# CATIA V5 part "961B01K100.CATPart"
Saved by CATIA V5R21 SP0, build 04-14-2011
Part number: 961B01K100
Bounding box of the stored display mesh (mm): x -18.1 to 18.1, y -25 to 75, z -10 to 4.5
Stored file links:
  C:\Users\ALI OZGUN\Desktop\alhan\961B01K100.CATPart
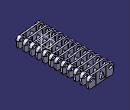
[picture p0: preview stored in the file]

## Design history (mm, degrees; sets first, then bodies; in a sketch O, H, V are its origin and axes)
Body1 (main body)
  Sketch1 on zx-plane, origin (0, 0, 0), H (-1, 0, 0), V (0, 0, 1)
    construction line L1 (-13.6, 0) -> (13.6, 0)
    point P1 (-13.6, 0)
    line L2 (-13.6, 4.5) -> (13.6, 4.5)
    line L3 (13.6, -4.5) -> (-13.6, -4.5)
    arc A1 centre (13.6, 0) radius 4.5 from (13.6, 4.5) to (13.6, -4.5) cw
    arc A2 centre (-13.6, 0) radius 4.5 from (-13.6, -4.5) to (-13.6, 4.5) cw
    distance L1 L2 = 4.5
    length L1 = 27.2
    distance P1 V = 13.6
    coincidence: P1 H
    horizontal: L1 H
    tangency: A1 L2, A2 L2, A1 L3, A2 L3
  Sketch2 on zx-plane, origin (0, 0, 0), H (-1, 0, 0), V (0, 0, 1)
    point P1 (-2.5, -4.5)
    line L1 (-2.5, -4.5) -> (-0.4806, 2.5379)
    point P2 (0, 4.2129)
    line L2 (0.4806, 2.5379) -> (2.5, -4.5)
    point P3 (2.5, -4.5)
    line L3 (2.5, -4.5) -> (-2.5, -4.5)
    arc A1 centre (0, 2.4) radius 0.5 from (-0.4806, 2.5379) to (0.4806, 2.5379) cw
    distance P3 P1 = 5
    distance L3 H = 4.5
    radius A1 = 0.5
    distance A1 L3 = 7.4
    horizontal: L3 H
    coincidence: L1 P2, L2 P2
    tangency: A1 L1, A1 L2
    symmetry: L1 L2 V
  Pad1: profile Sketch2, direction (0, 1, 0), length 25, mirrored extent
  Body2
    Pad2: profile Sketch6, direction (0, 0, 1), length 25, mirrored extent
    Pocket1: profile Sketch1, direction (0, -1, 0), length 25, outer side
    Fillet1: radius 5, on edge [face of Pad2 from Sketch6.L3 | face of Pad2 from Sketch6.L2]; edge [face of Pad2 from Sketch6.L8 | face of Pad2 from Sketch6.L7]; edge [face of Pad2 from Sketch6.L7 | face of Pad2 from Sketch6.L4]; edge [face of Pad2 from Sketch6.L2 | face of Pad2 from Sketch6.L1]
    RectPattern1: of the body so far, direction 1 instances 6, spacing 8.52, along yz-plane
    Sketch3 on face of Pad2 from Sketch6.L1, origin (0, -23.3, 0), H (1, 0, 0), V (0, 0, 1)
      arc A1 centre (-13.6, 0) radius 4.5 from (-9.1, 0) to (-18.1, 0) ccw
      line L1 (-9.2, 0) -> (-11.15, 0)
      arc A2 centre (-13.6, 0) radius 2.45 from (-11.15, 0) to (-16.05, 0) ccw
      reference projected arc E1 centre (-13.6, 0) radius 4.5 from (-13.6, 4.5) to (-13.6, -4.5) ccw from edge [face of Pocket1 from Sketch1.A1 | face of Pad2 from Sketch6.L1]
      point P5 (-16.05, 0)
      line L2 (-16.05, 0) -> (-18.1, 0)
      radius A1 = 4.5
      radius A2 = 2.45
      horizontal: L1 H, L2 H
      coincidence: L1 H, L1 P5, L1 L2
      concentricity: A1 E1
    Pad3: profile Sketch3, direction (0, -1, 0), length 1.7
    RectPattern2: of Pad3, direction 1 instances 6, spacing 8.52, along axis of face of Pocket1 from Sketch1.A2
    Sketch4 on face of RectPattern1, origin (0, 23.3, 0), H (-1, 0, 0), V (0, 0, 1)
      arc A1 centre (-13.6, 0) radius 4.5 from (-18.1, 0) to (-9.1, 0) cw
      line L1 (-18.1, 0) -> (-16.05, 0)
      arc A2 centre (-13.6, 0) radius 2.45 from (-16.05, 0) to (-11.15, 0) cw
      line L2 (-11.15, 0) -> (-9.1, 0)
      reference projected arc E1 centre (-13.6, 0) radius 4.5 from (-13.6, 4.5) to (-13.6, -4.5) ccw from edge [face of RectPattern1 | face of RectPattern1]
      reference projected line E2 (-7.6525, 4.5) -> (-13.6, 4.5) from edge [face of RectPattern1 | face of RectPattern1]
      radius A2 = 2.45
      distance L2 H = 0
      concentricity: A1 E1, A2 A1
      coincidence: L1 L2
      tangency: A1 E2
    Pad4: profile Sketch4, direction (0, 1, 0), length 1.7, opposite side length 1
    RectPattern3: of Pad4, direction 1 instances 6, spacing 8.52, along axis of face of RectPattern1 reversed
    Sketch5 on zx-plane, origin (0, 0, 0), H (-1, 0, 0), V (0, 0, 1)
      circle A1 centre (-13.6, 0) radius 2.45
      point P1 (-13.6, 0)
      circle A2 centre (13.6, 0) radius 2.4
      point P2 (13.6, 0)
      reference projected arc E1 centre (-13.6, 0) radius 2.45 from (-11.15, 0) to (-16.05, 0) ccw from edge [face of Pad4 from Sketch4.A2 | end face of Pad4]
      reference projected arc E2 centre (13.6, 0) radius 4.5 from (13.6, -4.5) to (13.6, 4.5) ccw from edge [face of RectPattern1 | face of RectPattern2]
      radius A2 = 2.4
      radius A1 = 2.45
      coincidence: P1 H, P2 H
      concentricity: A1 E1, A2 E2
    Pocket2: profile Sketch5, direction (0, -1, 0), length 32.7, mirrored extent
  Add1: tool Body2
  Body3
    Solid1: solid without history
  Add2: tool Body3
  Body4
    Solid2: solid without history
  Add3: tool Body4
  Body5
    Solid3: solid without history
  Add4: tool Body5
  Sketch6 on xy-plane, origin (0, 0, 0), H (1, 0, 0), V (0, 1, 0)
    line L1 (-19.0192, -23.3) -> (-7.5, -23.3)
    point P1 (-7.5, -23.3)
    line L2 (-7.5, -23.3) -> (7.5, -21.6)
    point P2 (7.5, -21.6)
    line L3 (7.5, -21.6) -> (20, -21.6)
    point P3 (20, -21.6)
    line L4 (7.3701, -19.3) -> (20, -19.3)
    point P4 (7.5, -19.3)
    construction line L5 (7.5, -21.6) -> (7.5, -19.3)
    construction line L6 (20, -21.6) -> (20, -19.3)
    line L7 (-7.759, -21.0146) -> (7.3701, -19.3)
    point P6 (-7.759, -21.0146)
    line L8 (-19.0192, -21.0146) -> (-7.759, -21.0146)
    line L9 (20, -19.3) -> (20, -21.6)
    line L10 (-19.0192, -21.0146) -> (-19.0192, -23.3)
    reference projected line E2 (-2.5, -25) -> (-0.4806, -25) from edge [start face of Pad1 | face of Pad1 from Sketch2.L2]
    distance P1 P2 H = 15
    distance L1 L3 = 1.7
    distance P1 V = 7.5
    distance P2 P3 = 12.5
    distance L3 L4 = 2.3
    distance L1 E2 = 1.7
    distance L10 L9 = 39.0192
    distance L8 L1 = 2.2854
    distance L7 L2 = 2.3
    horizontal: L1 H, L3 H
    perpendicularity: L5 L3, L5 L4, L6 L3, L6 L4
    coincidence: L8 P6, P4 L4, P6 L7
    vertical: L9 V, L10 V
